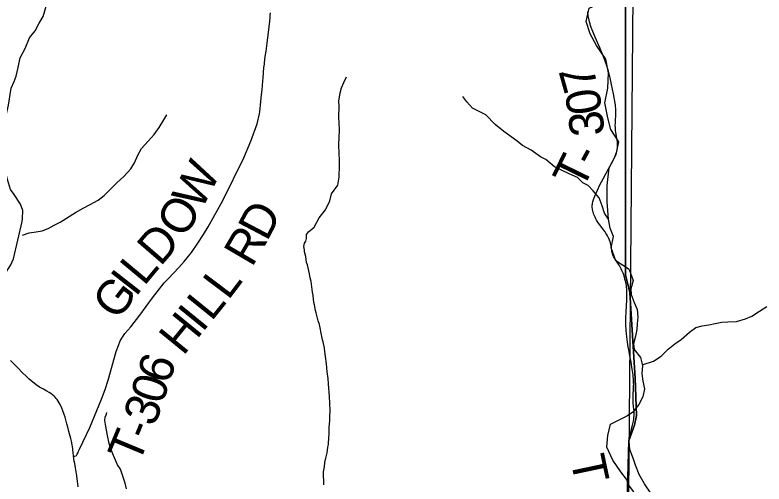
# Model space of a CAD drawing. Extents: x 0 to 34, y 0 to 22.
# Drawn here: x 6.729 to 7.967, y 15.821 to 16.596 of the extents above; entities that cross this region are included whole.
import ezdxf

# ---------------------------------------------------------------- set-up
doc = ezdxf.new("R2010")
doc.units = 0
for name, color, linetype in [('GM_X_Minor_River', 7, 'Continuous'), ('GM_X_Rail_Line', 7, 'Continuous'), ('GM_X_Section', 7, 'Continuous'), ('GM_X_Township_Road', 7, 'Continuous'), ('GM_X_Township_Road_Text', 7, 'Continuous'), ('SH_Cut_Line', 7, 'Continuous')]:
    doc.layers.add(name, color=color, linetype=linetype)

msp = doc.modelspace()

# ---------------------------------------------------------------- linework, layer by layer
at = {"layer": 'GM_X_Minor_River'}
for points in [[(6.7621, 16.5699), (6.769, 16.5824), (6.7752, 16.5933), (6.7845, 16.6258), (6.7948, 16.6319)], [(7.7097, 16.2585), (7.7075, 16.2873), (7.7071, 16.3142), (7.7109, 16.3434), (7.7223, 16.3655), (7.7265, 16.3863), (7.7132, 16.4065), (7.7087, 16.4258), (7.7033, 16.4509), (7.7083, 16.4751), (7.7094, 16.5002), (7.7049, 16.523), (7.6897, 16.5457), (7.6794, 16.5647), (7.6726, 16.5852), (7.6779, 16.6072), (7.7006, 16.6179), (7.7057, 16.622)], [(6.7408, 16.2545), (6.7412, 16.2598), (6.7417, 16.2727), (6.7382, 16.2833), (6.7277, 16.2995), (6.7215, 16.3077), (6.7163, 16.324), (6.7134, 16.3376), (6.7091, 16.3501), (6.7085, 16.3641), (6.709, 16.377), (6.7102, 16.4032), (6.7126, 16.42), (6.714, 16.4299), (6.7179, 16.447), (6.7224, 16.4748), (6.7276, 16.4863), (6.7309, 16.495), (6.7341, 16.5091), (6.7373, 16.5251), (6.7454, 16.5404), (6.7528, 16.5584), (6.7621, 16.5699)], [(7.2141, 16.2378), (7.2232, 16.2455), (7.2313, 16.2608), (7.2417, 16.2742), (7.2491, 16.2891), (7.252, 16.3002), (7.2624, 16.3148), (7.2645, 16.3277), (7.265, 16.3475), (7.2649, 16.3569), (7.2644, 16.3657), (7.2641, 16.3824), (7.2647, 16.393), (7.2649, 16.4059), (7.2644, 16.4173), (7.2642, 16.4272), (7.2643, 16.445), (7.2642, 16.4534), (7.2663, 16.4671), (7.2684, 16.4755), (7.2725, 16.4846), (7.2769, 16.4938)], [(7.7126, 16.2437), (7.7097, 16.2585), (7.7027, 16.2683), (7.6991, 16.2804), (7.6943, 16.2936), (7.6843, 16.3052), (7.6761, 16.3142), (7.6673, 16.3186), (7.6581, 16.3272), (7.6447, 16.3335), (7.6202, 16.3449), (7.6059, 16.3572), (7.5971, 16.3616), (7.5818, 16.3724), (7.5676, 16.3801), (7.5587, 16.3872), (7.5364, 16.4032), (7.5222, 16.4151), (7.5067, 16.4308), (7.4979, 16.4356), (7.4849, 16.4419), (7.4753, 16.4524), (7.469, 16.461)], [(6.7415, 16.2321), (6.7522, 16.236), (6.764, 16.2375), (6.7735, 16.2391), (6.7839, 16.2429), (6.7936, 16.2487), (6.8033, 16.2537), (6.829, 16.2697), (6.8414, 16.2765), (6.853, 16.2826), (6.8662, 16.2898), (6.876, 16.2979), (6.8883, 16.3097), (6.8978, 16.319), (6.9089, 16.3289), (6.9201, 16.3415), (6.9262, 16.3517), (6.9318, 16.3645), (6.938, 16.3753), (6.9488, 16.3876), (6.9591, 16.3987), (6.9672, 16.4099), (6.975, 16.4226), (6.9796, 16.4309)], [(6.5629, 15.9698), (6.5789, 15.9735), (6.5905, 15.9802), (6.6015, 15.9857), (6.6086, 15.9896), (6.6157, 15.9946), (6.6239, 16.0024), (6.6314, 16.0116), (6.6373, 16.0216), (6.6443, 16.0342), (6.6527, 16.0492), (6.6609, 16.0626), (6.6694, 16.0764), (6.6771, 16.0902), (6.6833, 16.1032), (6.6881, 16.1147), (6.6968, 16.1384), (6.7019, 16.1498), (6.7074, 16.1602), (6.7129, 16.1694), (6.7218, 16.1832), (6.7262, 16.1928), (6.7408, 16.2545)], [(7.7437, 16.1755), (7.7218, 16.1899), (7.7139, 16.2111), (7.7176, 16.2301), (7.7126, 16.2437)], [(7.2391, 15.8194), (7.2387, 15.8411), (7.2401, 15.8491), (7.2407, 15.8563), (7.2425, 15.8635), (7.2446, 15.8723), (7.246, 15.8818), (7.247, 15.8864), (7.2476, 15.8986), (7.2479, 15.9024), (7.2482, 15.9062), (7.2481, 15.9142), (7.249, 15.9256), (7.2493, 15.932), (7.2495, 15.9423), (7.2489, 15.9544), (7.2483, 15.9654), (7.2468, 15.9863), (7.2466, 15.9954), (7.2449, 16.0064), (7.2436, 16.0197), (7.2418, 16.0315), (7.2406, 16.0398), (7.2405, 16.0451), (7.238, 16.0557), (7.2368, 16.0591), (7.236, 16.0648), (7.2322, 16.0845), (7.2298, 16.0905), (7.2265, 16.1038), (7.2253, 16.1076), (7.2237, 16.117), (7.2228, 16.1208), (7.2215, 16.1326), (7.2206, 16.1379), (7.2184, 16.1557), (7.2168, 16.1617), (7.2156, 16.1682), (7.2123, 16.1829), (7.2107, 16.1871), (7.2094, 16.197), (7.2073, 16.2045), (7.2073, 16.2079), (7.2065, 16.2106), (7.206, 16.2132), (7.2071, 16.2186), (7.2093, 16.2224), (7.2104, 16.2266), (7.2103, 16.2297), (7.2106, 16.2331), (7.2141, 16.2378)], [(7.7437, 16.1755), (7.7503, 16.1571), (7.7467, 16.1434), (7.7472, 16.1339), (7.7519, 16.1207), (7.7569, 16.109), (7.7582, 16.0965), (7.7572, 16.0855), (7.7565, 16.076), (7.7544, 16.0653), (7.7507, 16.0524), (7.752, 16.0429), (7.7624, 16.0298), (7.7656, 16.0169), (7.7646, 16.0032), (7.7662, 15.9907), (7.769, 15.9782), (7.7665, 15.9649), (7.7599, 15.952), (7.7494, 15.9393), (7.7406, 15.9335)], [(7.7654, 16.0177), (7.7841, 16.0239), (7.7965, 16.032), (7.8081, 16.0439), (7.819, 16.0524), (7.8295, 16.0597), (7.8434, 16.072), (7.8539, 16.0797), (7.8641, 16.0825), (7.8755, 16.0837), (7.8861, 16.0861), (7.897, 16.0885), (7.9069, 16.089), (7.9209, 16.0895), (7.9357, 16.0939), (7.9462, 16.0982), (7.959, 16.1063), (7.9714, 16.1144)], [(6.9131, 15.8128), (6.911, 15.8222), (6.903, 15.8453), (6.8984, 15.8524), (6.8916, 15.8679), (6.8893, 15.8736), (6.8865, 15.8804), (6.8845, 15.8879), (6.8819, 15.9012), (6.8807, 15.9069), (6.8786, 15.9194), (6.8773, 15.9258), (6.8776, 15.9315), (6.8798, 15.9361), (6.8805, 15.9388)], [(7.7393, 15.829), (7.7301, 15.841), (7.7169, 15.8604), (7.7067, 15.8819), (7.7082, 15.9009), (7.7131, 15.9198), (7.7406, 15.9335)], [(7.7393, 15.829), (7.7412, 15.8209), (7.7505, 15.8085), (7.7643, 15.7961), (7.7766, 15.783), (7.7892, 15.7713), (7.7988, 15.7585), (7.7993, 15.7483), (7.8017, 15.7347), (7.811, 15.7234), (7.8138, 15.709), (7.815, 15.6992), (7.8197, 15.6856), (7.8214, 15.6693), (7.8231, 15.6568), (7.8232, 15.6473), (7.8226, 15.6344), (7.8094, 15.6251), (7.8019, 15.6096)]]:
    msp.add_lwpolyline(points, dxfattribs=at)
at = {"layer": 'GM_X_Rail_Line'}
for points in [[(5.9824, 16.6436), (7.149, 16.6283), (7.6814, 16.6224), (7.7376, 16.622), (7.7377, 16.1663), (7.7446, 16.1373), (7.7538, 15.9954), (7.756, 15.9342), (7.7526, 15.9181), (7.7434, 15.892), (7.7355, 15.6105), (7.8392, 15.6096), (8.369, 15.6108), (8.7708, 15.6025), (8.77, 15.1835), (8.767, 14.6265), (8.9, 14.624), (8.9, 20.9)], [(4.5781, 14.1), (8.76, 14.1), (8.766, 14.6043), (8.767, 14.6265), (8.77, 15.1835), (8.7708, 15.6025), (8.369, 15.6108), (7.8392, 15.6096), (7.7355, 15.6105), (7.7434, 15.892), (7.7526, 15.9181), (7.756, 15.9342), (7.7538, 15.9954), (7.7446, 16.1373), (7.7377, 16.1663), (7.7376, 16.622), (7.6814, 16.6224), (7.149, 16.6283), (5.9824, 16.6436)]]:
    msp.add_lwpolyline(points, dxfattribs=at)
at = {"layer": 'GM_X_Section'}
msp.add_lwpolyline([(7.7506, 16.628), (8.7751, 16.6184), (8.7763, 15.6092), (7.7414, 15.613)], close=True, dxfattribs=at)
at = {"layer": 'GM_X_Township_Road'}
for points in [[(6.8256, 15.8671), (6.8278, 15.8671), (6.8304, 15.8682), (6.8316, 15.8701), (6.833, 15.8731), (6.834, 15.8752), (6.8354, 15.8785), (6.8524, 15.914), (6.872, 15.9608), (6.8781, 15.9772), (6.8829, 15.9924), (6.8959, 16.0397), (6.8997, 16.05), (6.9026, 16.0572), (6.9064, 16.0635), (6.9106, 16.0697), (6.92, 16.0805), (6.9351, 16.1001), (6.9563, 16.1285), (6.9677, 16.1436), (6.9756, 16.1533), (6.9818, 16.1598), (6.9906, 16.1691), (6.9996, 16.1788), (7.0085, 16.1884), (7.0135, 16.1946), (7.0204, 16.2037), (7.0309, 16.2186), (7.0404, 16.2333), (7.0479, 16.2458), (7.0722, 16.2894), (7.107, 16.3601), (7.1184, 16.3873), (7.1288, 16.4161), (7.1331, 16.4325), (7.1335, 16.4359), (7.1341, 16.4413), (7.1348, 16.447), (7.1358, 16.4593), (7.1371, 16.4728), (7.1379, 16.4796), (7.1385, 16.4869), (7.1387, 16.4918), (7.1395, 16.5011), (7.1401, 16.509), (7.1409, 16.5146), (7.1412, 16.517), (7.1425, 16.5275), (7.1437, 16.5361), (7.1456, 16.5496), (7.1486, 16.5761), (7.1497, 16.586), (7.1503, 16.5918), (7.1506, 16.5957), (7.1508, 16.5997)], [(7.7436, 15.8915), (7.7442, 15.8965), (7.7452, 15.9013), (7.7462, 15.9055), (7.7472, 15.9096), (7.7494, 15.918), (7.7508, 15.9247), (7.7513, 15.9278), (7.7517, 15.9309), (7.7519, 15.9336), (7.752, 15.9364), (7.7519, 15.9408), (7.7515, 15.9451), (7.7511, 15.9482), (7.7504, 15.9556), (7.7502, 15.9581), (7.7501, 15.9609), (7.7501, 15.963), (7.7501, 15.965), (7.7502, 15.9671), (7.7504, 15.9711), (7.7508, 15.976), (7.751, 15.9778), (7.751, 15.9796), (7.7511, 15.9818), (7.7511, 15.9839), (7.7512, 15.986), (7.7511, 15.9877), (7.751, 15.9907), (7.7509, 15.9919), (7.7507, 15.9949), (7.7504, 15.9985), (7.7502, 16.001), (7.7497, 16.0051), (7.7494, 16.0075), (7.7488, 16.0109), (7.7483, 16.0138), (7.7468, 16.0222), (7.7449, 16.0328), (7.7437, 16.0396), (7.7423, 16.0474), (7.7409, 16.0553), (7.7398, 16.0639), (7.7394, 16.0697), (7.739, 16.0739), (7.7384, 16.0856), (7.7384, 16.0956), (7.7386, 16.1054), (7.7391, 16.1146), (7.7397, 16.125), (7.74, 16.1346), (7.7398, 16.1418), (7.7393, 16.1479), (7.7392, 16.1494), (7.739, 16.1507), (7.7387, 16.1521), (7.7384, 16.154), (7.7379, 16.1558), (7.7368, 16.1596), (7.7359, 16.1628), (7.7341, 16.1681), (7.7329, 16.1713), (7.7318, 16.1739), (7.7307, 16.1764), (7.7294, 16.1789), (7.7277, 16.1819), (7.7262, 16.1842), (7.7217, 16.1908), (7.7205, 16.1927), (7.719, 16.195), (7.718, 16.1969), (7.717, 16.199), (7.7162, 16.2014), (7.7155, 16.2036), (7.7152, 16.205), (7.7151, 16.2062), (7.7149, 16.2081), (7.7148, 16.209), (7.7147, 16.2099), (7.7146, 16.2109), (7.7144, 16.2125), (7.7142, 16.2138), (7.7128, 16.2192), (7.7123, 16.221), (7.712, 16.222), (7.7116, 16.223), (7.7109, 16.2251), (7.7101, 16.2268), (7.7081, 16.231), (7.7065, 16.2337), (7.7053, 16.2355), (7.7039, 16.2376), (7.7013, 16.241), (7.6968, 16.247), (7.6932, 16.252), (7.69, 16.2569), (7.6886, 16.2592), (7.6874, 16.2616), (7.6863, 16.2639), (7.6854, 16.2661), (7.6847, 16.2682), (7.6841, 16.2703), (7.6836, 16.2725), (7.6833, 16.2745), (7.6828, 16.2788), (7.6827, 16.2804), (7.6828, 16.2819), (7.683, 16.2835), (7.6832, 16.285), (7.6838, 16.2873), (7.6848, 16.2908), (7.687, 16.2966), (7.6912, 16.3062), (7.6954, 16.3152), (7.7005, 16.3252), (7.7095, 16.3415), (7.7167, 16.3545), (7.7194, 16.3601), (7.7217, 16.3659), (7.7232, 16.3706), (7.7241, 16.3748), (7.7243, 16.376), (7.7246, 16.3781), (7.7247, 16.3805), (7.7247, 16.3829), (7.7244, 16.3863), (7.724, 16.389), (7.7235, 16.3918), (7.7217, 16.4022), (7.7214, 16.4045), (7.7212, 16.4065), (7.721, 16.4084), (7.721, 16.4102), (7.7208, 16.414), (7.7209, 16.4171), (7.721, 16.4195), (7.7217, 16.4326), (7.7217, 16.4364), (7.7217, 16.4394), (7.7216, 16.4419), (7.7214, 16.4443), (7.721, 16.4477), (7.7206, 16.4505), (7.7178, 16.4658), (7.7148, 16.481), (7.7123, 16.4919), (7.7093, 16.5033), (7.7062, 16.5134), (7.7016, 16.5256), (7.6957, 16.5406), (7.6877, 16.5595), (7.6837, 16.5685), (7.681, 16.5755), (7.68, 16.5784), (7.6791, 16.5814), (7.6783, 16.5846), (7.6776, 16.5873), (7.6761, 16.5945), (7.6752, 16.6011)], [(6.8256, 15.8671), (6.8249, 15.8733), (6.8246, 15.8764), (6.8242, 15.8794), (6.8237, 15.8824), (6.8233, 15.8855), (6.8221, 15.8916), (6.8212, 15.8958), (6.818, 15.9078), (6.8161, 15.915), (6.8146, 15.9204), (6.8115, 15.9311), (6.81, 15.9358), (6.808, 15.9416), (6.8062, 15.9463), (6.8033, 15.9524), (6.8001, 15.9578), (6.7985, 15.9604), (6.797, 15.9624), (6.7954, 15.9644), (6.7936, 15.9661), (6.791, 15.9683), (6.7883, 15.9702), (6.7855, 15.972), (6.7814, 15.9744), (6.7759, 15.9774), (6.7695, 15.9811), (6.7638, 15.9848), (6.7603, 15.9873), (6.7555, 15.9913), (6.7523, 15.9942), (6.749, 15.9973), (6.7398, 16.0061), (6.735, 16.011), (6.7215, 16.0248)], [(7.8394, 15.6091), (7.8459, 15.625), (7.8491, 15.6365), (7.8508, 15.6474), (7.8508, 15.6564), (7.848, 15.6768), (7.8442, 15.6971), (7.8415, 15.7074), (7.839, 15.7149), (7.8349, 15.7243), (7.8299, 15.7343), (7.8197, 15.7532), (7.8148, 15.7613), (7.8105, 15.7676), (7.8037, 15.776), (7.7875, 15.7949), (7.7804, 15.804), (7.7688, 15.821), (7.7603, 15.8363), (7.7543, 15.8519), (7.7508, 15.8621), (7.7449, 15.8777), (7.7436, 15.8915)], [(6.8331, 15.8161), (6.8308, 15.8344), (6.8286, 15.8477), (6.8275, 15.8545), (6.8268, 15.8587), (6.8256, 15.8671)]]:
    msp.add_lwpolyline(points, dxfattribs=at)
at = {"layer": 'SH_Cut_Line'}
for points in [[(5.9824, 16.6436), (7.149, 16.6283), (7.6814, 16.6224), (7.7376, 16.622), (7.7377, 16.1663), (7.7446, 16.1373), (7.7538, 15.9954), (7.756, 15.9342), (7.7526, 15.9181), (7.7434, 15.892), (7.7355, 15.6105), (7.8392, 15.6096), (8.369, 15.6108), (8.7708, 15.6025), (8.77, 15.1835), (8.767, 14.6265), (8.9, 14.624), (8.9, 20.9)], [(4.5781, 14.1), (8.9, 14.1), (8.9, 14.624), (8.767, 14.6265), (8.77, 15.1835), (8.7708, 15.6025), (8.369, 15.6108), (7.8392, 15.6096), (7.7355, 15.6105), (7.7434, 15.892), (7.7526, 15.9181), (7.756, 15.9342), (7.7538, 15.9954), (7.7446, 16.1373), (7.7377, 16.1663), (7.7376, 16.622), (7.6814, 16.6224), (7.149, 16.6283), (5.9824, 16.6436)]]:
    msp.add_lwpolyline(points, dxfattribs=at)

# ---------------------------------------------------------------- texts
at = {"layer": 'GM_X_Township_Road_Text'}
for s, rotation, p in [('7', 105.6764, (7.6928, 16.4779)), ('0', 98.5311, (7.6995, 16.436)), ('3', 95.3688, (7.7032, 16.3981)), ('T', 63.9676, (7.6665, 16.3048)), ('-', 61.3303, (7.6848, 16.3423)), ('W', 62.4239, (7.0363, 16.2713)), ('O', 58.1517, (7.0077, 16.2248)), ('D', 62.2872, (7.1452, 16.2203)), ('D', 49.1043, (6.9691, 16.1791)), ('R', 59.6788, (7.1203, 16.1776)), ('L', 50.2136, (6.9421, 16.1467)), ('I', 52.0216, (6.9281, 16.1286)), ('L', 53.0507, (7.0812, 16.1232)), ('G', 52.2209, (6.8975, 16.0892)), ('L', 51.1093, (7.0533, 16.0884)), ('I', 50.8636, (7.0384, 16.0701)), ('H', 50.8003, (7.0067, 16.0313)), ('6', 71.2014, (6.9828, 15.984)), ('0', 73.1596, (6.9729, 15.951)), ('3', 68.8954, (6.9588, 15.914)), ('-', 67.7199, (6.9494, 15.8912)), ('T', 67.4035, (6.933, 15.8517)), ('T', 281.9706, (7.6462, 15.8627))]:
    msp.add_text(s, height=0.0568, rotation=rotation, dxfattribs=at).set_placement(p)

doc.saveas('drawing.dxf')
